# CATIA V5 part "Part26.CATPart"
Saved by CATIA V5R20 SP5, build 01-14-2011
Part number: Part26
Material "Water": density 1000 kg/m3
Bounding box of the stored display mesh (mm): x -1.919 to 1.919, y -2 to 2, z -1.919 to 1.919
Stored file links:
  D:\新建文件夹\Part26.CATPart
  C:\Program Files\Dassault Systemes\B20\intel_a\startup\materials\Catalog.CATMaterial
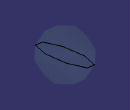
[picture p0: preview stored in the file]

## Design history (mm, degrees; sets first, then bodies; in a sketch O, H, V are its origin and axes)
Body1 (main body), material "Water"
  Sketch1 on xy-plane, origin (0, 0, 0), H (1, 0, 0), V (0, 1, 0)
    arc A1 centre (0, 0) radius 2 from (0, -2) to (0, 2) ccw
    axis line L1 (0, 2.6954) -> (0, -2.923)
    point P1 (0, 2.6954)
    point P3 (0, 2)
    point P4 (0, -2)
    radius A1 = 2
    coincidence: P1 V, L1 P3, L1 P4
    vertical: L1 V
  Shaft1: profile Sketch1, axis Sketch1.L1, angle 360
